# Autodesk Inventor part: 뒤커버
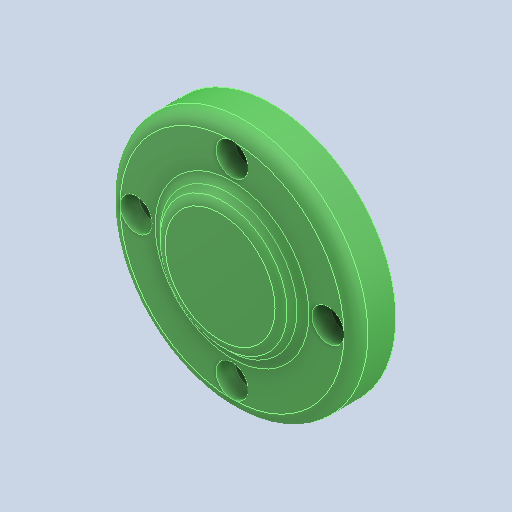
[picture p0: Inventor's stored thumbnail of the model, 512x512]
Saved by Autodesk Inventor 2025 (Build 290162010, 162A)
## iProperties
Created: 2024-07
Part Number: 뒤커버
Material: 알루미늄 6061
Document SubType Name: Modeling
Designer: Admin
Density: 2.71 g/cm^3
Appearance: 기본값
Author: jhkim
Sending System: Autodesk Inventor 2025
Preprocessor: ST-DEVELOPER v20
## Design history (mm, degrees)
feature "솔리드1"
node "솔리드2"
